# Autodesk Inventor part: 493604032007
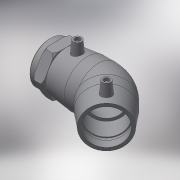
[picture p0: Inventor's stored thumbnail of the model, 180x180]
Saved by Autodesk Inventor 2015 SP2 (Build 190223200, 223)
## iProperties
Created: 2017-06
Part Number: 493604032007
Material: Generic
Description: PLASSON 45° ELBOW TRANSITION FEMALE 32-3/4"
Document SubType Name: Modeling
Designer: KIM
Mass: 107.978 g
Surface Area: 333.409 cm^2
Volume: 107.978 cm^3
Density: 1 g/cm^3
Appearance: Default
Author: KIM
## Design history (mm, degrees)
derived "493604.ipt"
feature "Solid1::493604.ipt"
tag "TaggingFeature1"
body "Solid1"
other parameters: "d2" = 44, "d4" = 23.75, "d5" = 39.6, "d8" = 168 deg, "d10" = 15.6, "d11" = 5.2, "d29" = 43, "d30" = 15, "d31" = 33.25, "d34" = 5 deg, "d41" = 4, "d42" = 14, "d43" = 0, "d49" = 32, "d50" = 27.2, "d51" = 15.6, "d52" = 39, "d54" = 135 deg, "d86" = 19.8, "d87" = 135 deg, "d88" = 95, "d90" = 39, "d91" = 0, "d92" = 39, "d93" = 0, "d101" = 3, "d102" = 0, "d107" = 0.1, "d108" = 23, "d110" = 25, "d112" = 39.6, "d113" = 24.117, "d114" = 22.5, "d128" = 15, "d129" = 0, "d132" = 1.6, "d133" = 45 deg, "d134" = 45 deg, "d136" = 0.96, "d_" = 32, "L_1" = 39, "D_" = 23, "A_" = 43, "d_2" = 12, "L_2" = 25, "Rp_" = 24.117, "D_1" = 44
